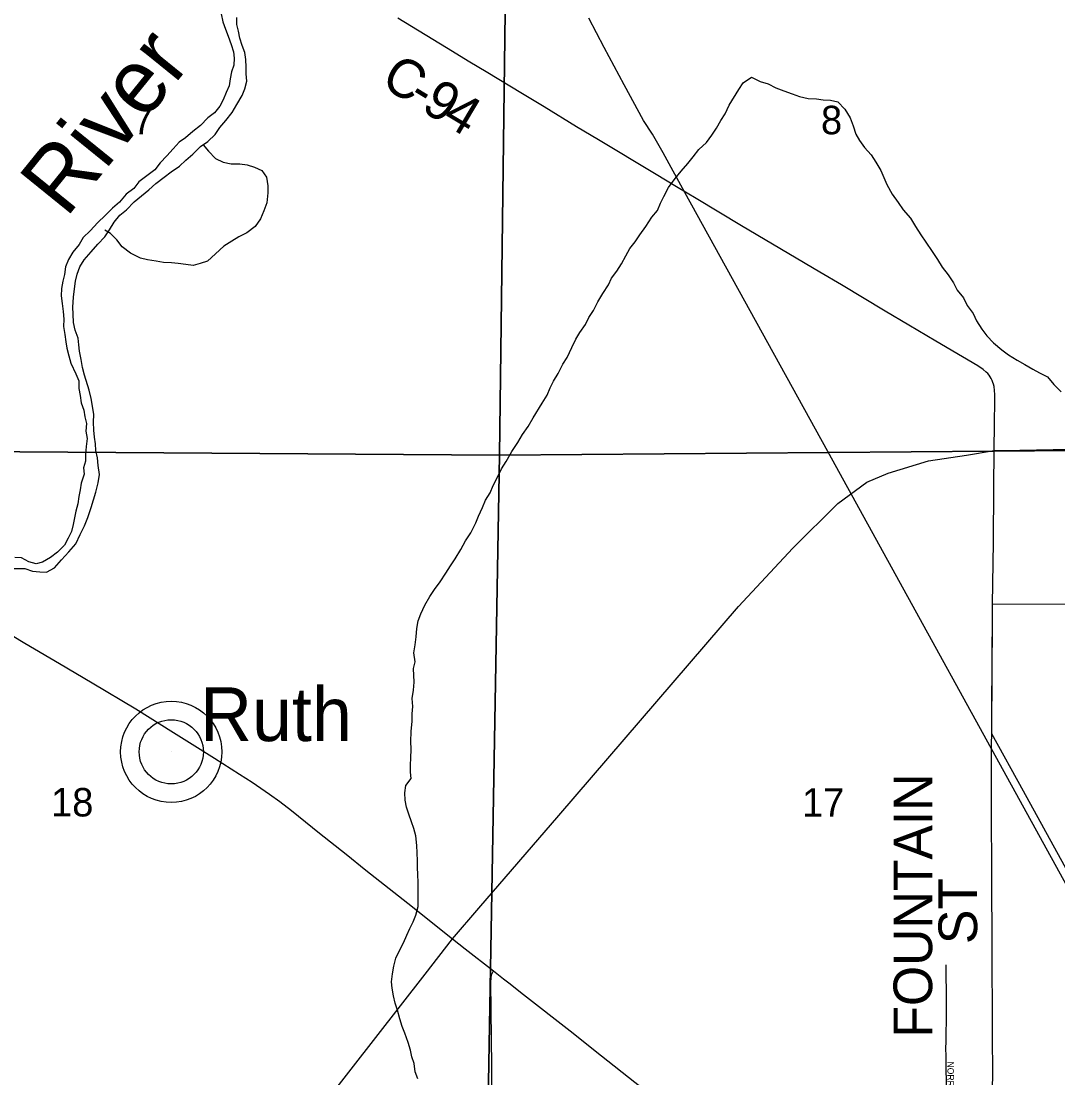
# Model space of a CAD drawing. Extents: x 1584893 to 1934202, y 663575 to 1091909.
# Drawn here: x 1779115 to 1787160, y 948263 to 956462 of the extents above; entities that cross this region are included whole.
import ezdxf

# ---------------------------------------------------------------- set-up
doc = ezdxf.new("R2010")
doc.units = 0
for name, color, linetype in [('GM_X_Corporation', 7, 'Continuous'), ('GM_X_County_Road', 7, 'Continuous'), ('GM_X_County_Road_Text', 7, 'Continuous'), ('GM_X_County_ROW', 7, 'Continuous'), ('GM_X_Major_River', 7, 'Continuous'), ('GM_X_Major_River_Text', 7, 'Continuous'), ('GM_X_Minor_River', 7, 'Continuous'), ('GM_X_Rail_Line', 7, 'Continuous'), ('GM_X_Section', 7, 'Continuous'), ('GM_X_Section_Text', 7, 'Continuous'), ('GM_X_State_Route', 7, 'Continuous'), ('GM_X_Township_Subdivision', 7, 'Continuous'), ('GM_X_Township_Subdivision_Text', 7, 'Continuous'), ('GM_X_Unincorporated', 7, 'Continuous'), ('GM_X_Unincorporated_Location', 7, 'Continuous'), ('GM_X_Unincorporated_Text', 7, 'Continuous')]:
    doc.layers.add(name, color=color, linetype=linetype)

msp = doc.modelspace()

# ---------------------------------------------------------------- linework, layer by layer
at = {"layer": 'GM_X_Corporation'}
msp.add_lwpolyline([(1788342.3, 947851), (1786892.8, 950488), (1786647.5, 950933.2), (1786652.7, 951937.3), (1787929.2, 951942.6)], dxfattribs=at)
at = {"layer": 'GM_X_County_Road'}
for points in [[(1786664.9, 953129.8), (1786667.1, 953339.7), (1786671, 953515.1), (1786671.1, 953564.2), (1786669.1, 953596.7), (1786664.6, 953628.6), (1786660.9, 953644.3), (1786656.1, 953659.6), (1786650.3, 953674.5), (1786643.2, 953688.8), (1786635.1, 953702.6), (1786625.9, 953715.7), (1786615.7, 953728), (1786604.6, 953739.5), (1786580, 953760.3), (1786539.6, 953787.7), (1786419.1, 953857), (1786214.2, 953978.3), (1786002.7, 954104.1), (1785819.6, 954213.2), (1785481.6, 954415.1), (1785312.5, 954515.8), (1784705.6, 954875.3), (1784353.3, 955085.2), (1784212.8, 955169.7), (1784029.7, 955279.1), (1783594.5, 955541.9), (1783425.1, 955642.2), (1783173.3, 955796.2), (1783004.8, 955898.1), (1782724.5, 956068.3), (1782597.6, 956144), (1782416.2, 956256), (1782037.5, 956485.7)], [(1786652.7, 951937.3), (1786659.4, 952416.3), (1786661.9, 952842.8), (1786664.9, 953129.8)], [(1786664.9, 953129.8), (1786700.7, 953130.6), (1786864.8, 953134.2), (1787767.6, 953150.5), (1787923, 953151.9), (1787938.4, 953151.8)], [(1786647.5, 950933.2), (1786648, 951069), (1786647.7, 951183.7), (1786650.5, 951429.2), (1786652.1, 951773.1), (1786652.7, 951937.3)], [(1786653.5, 948531.5), (1786652.1, 948827.4), (1786651.2, 949090.1), (1786649.7, 949254.3), (1786649.2, 949484.3), (1786648.9, 949615.6), (1786647.6, 949845.6), (1786646.4, 950038.8), (1786645.6, 950141), (1786644.6, 950535.2), (1786644.2, 950650.2), (1786644.2, 950754.1), (1786645.2, 950852.1), (1786647.5, 950933.2)], [(1782667.7, 949579.8), (1783286.8, 950299.6)], [(1782463.4, 949342.4), (1782667.7, 949579.8)], [(1782249.8, 949068.1), (1782463.4, 949342.4)], [(1780521.1, 945203.3), (1780551.6, 945810.5), (1780556.4, 946045.3), (1780558, 946211.4), (1780562.7, 946340.8), (1780573.9, 946473.4), (1780594.7, 946614), (1780634.6, 946773.7), (1780676.2, 946911.1), (1780732.1, 947035.6), (1780786.4, 947149.1), (1780853.5, 947265.7), (1780954.1, 947407.8), (1781083.5, 947570.8), (1782249.8, 949068.1)], [(1782700.8, 945177.9), (1782701.5, 945201.7), (1782713.6, 945663.6), (1782716.9, 945842.1), (1782728.5, 946250.7), (1782735.1, 946484.5), (1782742.7, 946792.9), (1782755.9, 947333.9), (1782763.5, 947629), (1782768.5, 947842.1), (1782767.8, 948153.6), (1782767, 948350.4), (1782760.3, 949006.4), (1782761.3, 949039.1), (1782762.2, 949049), (1782764.2, 949057.7), (1782767.8, 949067.3), (1782773, 949079.3), (1782779.5, 949094.2)], [(1786651.8, 947841.9), (1786651.8, 947982.3), (1786652.7, 948122.4), (1786654.3, 948351.1), (1786653.5, 948531.5)]]:
    msp.add_lwpolyline(points, dxfattribs=at)
at = {"layer": 'GM_X_County_ROW'}
msp.add_lwpolyline([(1783286.8, 950299.6), (1784680.7, 951920.3), (1785102.4, 952373.9), (1785453.8, 952718.9), (1785677.4, 952885.1), (1785843.5, 952955.3), (1786156.6, 953051.2), (1786450.5, 953095.9), (1786664.9, 953129.8)], dxfattribs=at)
at = {"layer": 'GM_X_Major_River'}
for points in [[(1780667.8, 956519.8), (1780678.8, 956457.5), (1780699.8, 956399.1), (1780720.9, 956346.7), (1780743.8, 956282.3), (1780762.7, 956223.9), (1780767.9, 956173.8), (1780765.1, 956121.8), (1780746.2, 956070.1), (1780737.3, 956014.2), (1780728.4, 955960.3), (1780705.6, 955908.6), (1780682.7, 955853), (1780657.9, 955801.4), (1780615.2, 955750.1), (1780562.6, 955710.9), (1780505.7, 955651.9), (1780447.1, 955604.8), (1780390.4, 955557.8), (1780339.9, 955522.6), (1780295.1, 955471.3), (1780246.3, 955416.1), (1780193.5, 955363), (1780152.7, 955309.7), (1780090.1, 955262.7), (1780029.4, 955215.7), (1779988.6, 955164.4), (1779930, 955119.3), (1779877.1, 955058.2), (1779824.4, 955011.1), (1779767.6, 954954), (1779710.8, 954900.9), (1779649.8, 954835.9), (1779597.1, 954784.8), (1779564.2, 954729.3), (1779515.3, 954670.1), (1779482.4, 954612.6), (1779459.5, 954555), (1779450.6, 954497.1), (1779437.7, 954445.2), (1779428.8, 954387.3), (1779425.9, 954331.4), (1779432.9, 954271.2), (1779441.8, 954209), (1779444.8, 954148.9), (1779443.9, 954092.9), (1779452.8, 954030.7), (1779461.9, 953974.4), (1779469, 953924.3), (1779486, 953865.9), (1779501, 953807.6), (1779539.6, 953724.9), (1779562.7, 953672.5), (1779561.7, 953612.4), (1779572.8, 953558.2), (1779579.8, 953502), (1779600.8, 953443.6), (1779609.9, 953393.4), (1779621.1, 953341.2), (1779618.1, 953281.2), (1779627.1, 953223), (1779620.1, 953163.1), (1779615.1, 953101.1), (1779614.2, 953049.1), (1779599.4, 952997.3), (1779604.5, 952947.2), (1779581.4, 952877.5), (1779572.6, 952825.6), (1779563.7, 952773.7), (1779554.8, 952715.8), (1779539.9, 952660), (1779518.2, 952556.3), (1779505.3, 952502.5), (1779478.5, 952450.9), (1779451.7, 952395.4), (1779396.9, 952342.2), (1779342.3, 952301.2), (1779281.8, 952264.2), (1779231.7, 952251), (1779174.1, 952268), (1779116.7, 952297), (1779064.8, 952299.9)], [(1779035.5, 952216.3), (1779143.3, 952214.5), (1779202.8, 952195.5), (1779258.6, 952190.5), (1779312.4, 952185.6), (1779374.9, 952220.5), (1779427.9, 952283.7), (1779484.8, 952344.8), (1779539.7, 952405.9), (1779572.8, 952479.3), (1779605.9, 952546.8), (1779632.9, 952610.4), (1779658.1, 952688), (1779677.1, 952747.8), (1779694.1, 952807.5), (1779713.2, 952879.3), (1779722.3, 952945.2), (1779711.5, 953015.4), (1779706.4, 953073.5), (1779693.4, 953131.8), (1779692.3, 953181.9), (1779685.2, 953234), (1779678.1, 953288.2), (1779675.1, 953350.3), (1779678.1, 953410.3), (1779670.9, 953460.5), (1779658.2, 953534.7), (1779643.3, 953599), (1779605.3, 953715.8), (1779590.3, 953774.1), (1779579.4, 953836.3), (1779568.4, 953900.6), (1779561.3, 953950.7), (1779558.2, 954002.8), (1779535.2, 954065.3), (1779520.2, 954123.6), (1779519.3, 954189.6), (1779516.2, 954243.7), (1779521.5, 954321.7), (1779528.6, 954385.7), (1779535.6, 954445.6), (1779550.4, 954499.3), (1779569.3, 954557.1), (1779604.2, 954610.5), (1779659.1, 954671.6), (1779710, 954730.8), (1779764.8, 954787.9), (1779801.7, 954843.3), (1779836.6, 954902.8), (1779881.4, 954958), (1779932, 954999.2), (1779990.9, 955060.2), (1780047.6, 955107.3), (1780106.2, 955154.3), (1780161, 955203.4), (1780225.6, 955252.4), (1780278.2, 955293.5), (1780342.8, 955336.4), (1780393.5, 955383.6), (1780448.2, 955430.7), (1780507, 955489.7), (1780563.6, 955528.8), (1780620.4, 955583.8), (1780657.2, 955637.3), (1780702, 955692.5), (1780753, 955753.7), (1780789.9, 955815.1), (1780831, 955884.5), (1780851.8, 955938.2), (1780866.8, 955995.9), (1780861.7, 956054.1), (1780860.6, 956106.1), (1780859.6, 956164.2), (1780850.5, 956218.4), (1780829.4, 956272.8), (1780812.4, 956329.2), (1780801.4, 956385.4), (1780788.2, 956435.7), (1780789.1, 956489.7)]]:
    msp.add_lwpolyline(points, dxfattribs=at)
at = {"layer": 'GM_X_Minor_River'}
for points in [[(1784009.2, 954941), (1784054, 954992.2), (1784076.9, 955049.9), (1784101.7, 955101.5), (1784138.8, 955170.9), (1784189.9, 955240.1), (1784236.8, 955299.3), (1784289.6, 955356.5), (1784330.4, 955409.8), (1784373.3, 955467.1), (1784434.1, 955520.1), (1784474.9, 955577.4), (1784511.8, 955632.8), (1784544.7, 955690.3), (1784579.5, 955743.8), (1784610.5, 955809.3), (1784684.4, 955932.1), (1784717.2, 955983.6), (1784781.8, 956026.5), (1784851.1, 955993.3), (1784910.7, 955976.2), (1784972.1, 955945.2), (1785033.6, 955922.1), (1785097.1, 955899), (1785154.6, 955878), (1785222.2, 955862.8), (1785288.1, 955859.6), (1785339.8, 955852.8), (1785395.7, 955849.8), (1785453.4, 955836.8), (1785506.3, 955779.8), (1785547.1, 955713.1), (1785572, 955650.6), (1785592.9, 955586.2), (1785622, 955535.6), (1785659.1, 955482.9), (1785710, 955424), (1785747, 955367.3), (1785785.9, 955304.6), (1785808.9, 955250.2), (1785834, 955193.7), (1785874.7, 955120.9), (1785919.5, 955056.1), (1785958.5, 954997.4), (1786017.3, 954934.3), (1786056.1, 954869.6), (1786097, 954804.8), (1786136, 954748.1), (1786184.7, 954675.2), (1786225.6, 954612.5), (1786262.5, 954553.8), (1786309.4, 954494.9), (1786350.3, 954432.2), (1786379.3, 954375.6), (1786428.2, 954316.7), (1786457.2, 954256.2), (1786502.1, 954193.4), (1786529.1, 954136.8), (1786569.9, 954072.1), (1786609, 954021.4), (1786660, 953966.4), (1786724.9, 953911.3), (1786778.2, 953872.3), (1786845.4, 953831.1), (1786904.7, 953798.1), (1786966, 953761), (1787017.4, 953734.1), (1787078.8, 953703), (1787127.7, 953642.1), (1787184.6, 953585.1)], [(1780526.9, 955503.4), (1780568.3, 955452.6), (1780623.3, 955395.7), (1780682.7, 955368.6), (1780744.4, 955355.5), (1780812.2, 955356.4), (1780870, 955347.4), (1780925.6, 955330.4), (1780983, 955303.4), (1781018.1, 955252.8), (1781029, 955184.5), (1781030.1, 955130.4), (1781020.8, 955052.5), (1780997.8, 954990.9), (1780972.8, 954927.3), (1780931.9, 954869.9), (1780865.3, 954821), (1780804.9, 954790), (1780750.4, 954754.9), (1780687.8, 954716), (1780623, 954657.1), (1780560.2, 954600.1), (1780504, 954581), (1780449.8, 954566), (1780394.1, 954574.9), (1780334.3, 954582), (1780282.5, 954586.8), (1780220.6, 954589.9), (1780162.9, 954600.9), (1780095.2, 954610.1), (1780041.5, 954623), (1779962.3, 954662.4), (1779899.3, 954711.5), (1779858.2, 954764.3), (1779809.2, 954815.2), (1779763.7, 954840)], [(1782034.8, 948788), (1782017.8, 948842.4), (1782004.7, 948898.7), (1781993.7, 948958.9), (1781988.6, 949009), (1781995.6, 949070.9), (1782006.6, 949130.8), (1782023.5, 949190.6), (1782052.6, 949256.1), (1782081.4, 949311.7), (1782108.3, 949369.2), (1782131.2, 949422.9), (1782158, 949474.5), (1782178.8, 949526.2), (1782195.9, 949591.9), (1782194.9, 949656), (1782195.8, 949708), (1782196.9, 949778), (1782194, 949842.2), (1782190.9, 949894.2), (1782191.8, 949946.3), (1782186.8, 950008.4), (1782185.8, 950066.5), (1782177, 950140.7), (1782162, 950199), (1782144.9, 950249.3), (1782123.9, 950309.7), (1782104.9, 950364.1), (1782093.8, 950418.3), (1782092.7, 950474.4), (1782099.7, 950532.3), (1782140.5, 950585.7), (1782137.3, 950635.8), (1782136.2, 950691.8), (1782139.1, 950743.8), (1782140.3, 950813.9), (1782139.2, 950871.9), (1782142.5, 950949.9), (1782149.8, 951029.9), (1782148.8, 951087.9), (1782153.7, 951143.9), (1782148.8, 951206), (1782159.8, 951271.9), (1782164.9, 951333.9), (1782158.6, 951440), (1782171.5, 951491.9), (1782162.6, 951560.1), (1782171.6, 951622), (1782180.7, 951685.9), (1782185.7, 951749.8), (1782194.7, 951809.7), (1782215.5, 951863.4), (1782248.6, 951930.9), (1782285.7, 951998.3), (1782322.5, 952051.7), (1782365.4, 952113), (1782410.4, 952180.3), (1782447.3, 952235.7), (1782484.1, 952289.1), (1782527.2, 952362.4), (1782562.3, 952429.9), (1782603.3, 952493.2), (1782644.4, 952568.6), (1782663.3, 952620.3), (1782696.3, 952687.8), (1782719.2, 952745.4), (1782754.1, 952802.9), (1782779, 952858.5), (1782807.9, 952918), (1782843, 952987.5), (1782879.9, 953044.9), (1782923.1, 953124.2), (1782968.2, 953193.5), (1783005.2, 953254.9), (1783050.1, 953318.2), (1783089.2, 953385.6), (1783158.9, 953498.5), (1783195.9, 953559.9), (1783220.8, 953617.5), (1783245.6, 953669.1), (1783282.5, 953728.5), (1783319.6, 953799.9), (1783352.4, 953851.4), (1783387.6, 953928.9), (1783418.6, 953994.4), (1783449.4, 954045.9), (1783494.4, 954109.2), (1783519.2, 954162.8), (1783556.1, 954218.2), (1783589.1, 954283.7), (1783630.1, 954349), (1783673.2, 954416.3), (1783696, 954468), (1783738.8, 954523.3), (1783773.7, 954578.7), (1783808.6, 954640.2), (1783839.5, 954697.7), (1783880.3, 954749), (1783915.2, 954804.5), (1783962.1, 954869.7), (1784009.2, 954941)], [(1782193.7, 948256.9), (1782172.6, 948309.3), (1782163.7, 948373.5), (1782146.6, 948425.8), (1782135.5, 948478.1), (1782118.5, 948538.4), (1782091.8, 948610.9), (1782072.6, 948661.3), (1782053.7, 948721.7), (1782034.8, 948788)]]:
    msp.add_lwpolyline(points, dxfattribs=at)
at = {"layer": 'GM_X_Rail_Line'}
msp.add_lwpolyline([(1789400.6, 945815.7), (1789127.2, 946312.4), (1788279, 947851.2), (1787937.1, 948469), (1787819.8, 948676.5), (1787624.4, 949012.2), (1787505.6, 949248.9), (1787424.3, 949403.4), (1787265.8, 949688.4), (1785374.8, 953122.4), (1784266.3, 955133.8), (1784098.1, 955439.7), (1784015.4, 955585.7), (1783944.2, 955691.7), (1783794.4, 955967.2), (1783640.1, 956257.8), (1783519.3, 956485.2)], dxfattribs=at)
at = {"layer": 'GM_X_Section'}
for points in [[(1777321.1, 958467.5), (1782893.3, 958359.1), (1782828, 953093.9), (1777243.3, 953134.1), (1777240.1, 953230.1)], [(1782893.3, 958359.1), (1787950.9, 958440.7), (1787937.3, 953135.4), (1782828, 953093.9)], [(1777243.3, 953134.1), (1782828, 953093.9), (1782733.9, 947785.7), (1777169.6, 947879.7), (1777170, 947933.7)], [(1782828, 953093.9), (1787937.3, 953135.4), (1787881.1, 947818.8), (1782733.9, 947785.7)]]:
    msp.add_lwpolyline(points, close=True, dxfattribs=at)
at = {"layer": 'GM_X_State_Route'}
for points in [[(1778833.5, 951821.8), (1779143.5, 951637.1), (1779411.7, 951478.3), (1779666.6, 951329.1), (1780003.9, 951125.9), (1780296.1, 950943.2), (1780421.1, 950864.8), (1780615.9, 950743.1), (1780809.9, 950620.1), (1780906.7, 950558.2), (1781042.3, 950465.6), (1781121.8, 950407.3), (1781212.5, 950336.6), (1781430.4, 950162.6), (1781635.8, 949999), (1781789.2, 949875.8), (1782115.5, 949617.6)], [(1782115.5, 949617.6), (1782463.4, 949342.4), (1782561.2, 949265.2), (1782779.5, 949094.2), (1782858.3, 949032.5), (1782900, 948999.5)], [(1782900, 948999.5), (1783012.6, 948910.3), (1783374.3, 948627.1), (1783619.2, 948434.3), (1783876.2, 948230.3), (1784147.8, 948018.3), (1784328.5, 947874.6)]]:
    msp.add_lwpolyline(points, dxfattribs=at)
at = {"layer": 'GM_X_Township_Subdivision'}
for points in [[(1786292.5, 948533.2), (1786294.2, 948618), (1786295.1, 948700.2), (1786295.7, 948765.7), (1786295.1, 948879.5), (1786293.1, 949108.1), (1786293.7, 949140.4)], [(1786301.9, 947838), (1786299.3, 947862.1), (1786297.7, 947879.6), (1786294.8, 947932.4), (1786294.6, 948144.1), (1786293.3, 948422.2), (1786291.9, 948504), (1786292.5, 948533.2)]]:
    msp.add_lwpolyline(points, dxfattribs=at)
at = {"layer": 'GM_X_Unincorporated'}
for radius in [392.8, 249]:
    msp.add_circle((1780279.8, 950792.6), radius, dxfattribs=at)
at = {"layer": 'GM_X_Unincorporated_Location'}
msp.add_line((1780279.8, 950792.6), (1780279.8, 950792.6), dxfattribs=at)

# ---------------------------------------------------------------- texts
at = {"layer": 'GM_X_County_Road_Text'}
for s, rotation, p in [('C', 328.44518, (1781894.1, 955967.3)), ('9', 328.57659, (1782209.7, 955773.6)), ('-', 328.47823, (1782104.2, 955838.3)), ('4', 329.21652, (1782370.5, 955675.4)), ('FOUNTAIN', 90, (1786184.7, 948575.1)), ('ST', 90, (1786533.7, 949301.1))]:
    msp.add_text(s, height=300, rotation=rotation, dxfattribs=at).set_placement(p)
at = {"layer": 'GM_X_Major_River_Text'}
msp.add_text('River', height=500.11, rotation=51.01541, dxfattribs=at).set_placement((1779463.4, 954927.8))
at = {"layer": 'GM_X_Section_Text'}
for s, p in [('7', (1779980.1, 955583)), ('8', (1785321.7, 955584.6)), ('18', (1779346.5, 950291.4)), ('17', (1785174.3, 950289.8))]:
    msp.add_text(s, height=221, rotation=0.00001, dxfattribs=at).set_placement(p)
at = {"layer": 'GM_X_Township_Subdivision_Text'}
msp.add_text('NORRIS ST', height=50, rotation=270, dxfattribs=at).set_placement((1786303.5, 948390.3))
at = {"layer": 'GM_X_Unincorporated_Text'}
msp.add_text('Ruth', height=417, rotation=0.00001, dxfattribs=at).set_placement((1780503.7, 950876.1))

doc.saveas('drawing.dxf')
